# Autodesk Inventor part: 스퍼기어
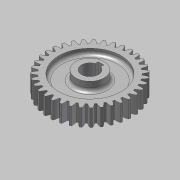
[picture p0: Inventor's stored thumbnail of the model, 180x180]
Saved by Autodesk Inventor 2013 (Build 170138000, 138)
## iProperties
Created: 2013-08
Part Number: 스퍼기어
Material: 강
Document SubType Name: Modeling
Designer: 한국산업디자인학원
Categories: <?xml version="1.0" encoding="UTF-16"?> <MemberInstance><Categories><FamilyTemplate><FamilyTemplateParameter ValueType="xs:double" Id="1" ObjectReferenceKey="da
Density: 1 g/cm^3
CustomPartVersion: 1
Author: 한국산업디자인학원
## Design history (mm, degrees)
sketch "Sketch1"
  geometry: C1 r 37 at (0, 0)
  constraints: 1 centre point
  dimensions: "d0" = 74 diameter of C1 (= da_da)
extrude "Extrusion1" new body sketch "Sketch1" distance "d1" = 15 (= da_b); taper "d2" = 0 deg
workplane "Work Plane2"
feature "피치 지름" dims "d4" = 10, "d5" = 0
workplane "Work Plane8"
workplane "Work Plane9"
feature "스퍼 기어" dims "da_b" = 15, "da_d" = 70, "da_aw" = 70, "da_da" = 74, "da_df" = 65, "da_dw" = 70, angle "da_beta" = 0 deg, "da_lefttooth" = 0, "da_righttooth" = 0
node "작업 평면11"
sketch "스케치3"
  geometry: C1 r 12.5 at (0, 0); 1 further point
  constraints: 1 centre point, 1 coincident
  dimensions: "d50" = 25 diameter of C1
extrude "돌출2" join sketch "스케치3" distance "d51" = 31; taper "d52" = 0 deg
hole "구멍1" diameter "d55" = 15; stored, may be unused: countersink angle "d59" = 90 deg, drill point angle "d61" = 0 deg; dims "d53" = 10, "d54" = 10, "d56" = 6, "d57" = 4, "d58" = 2, "d60" = 8
sketch "스케치4"
  geometry: L1 (0, 28.305)-(0, -28.305); L2 (35, 15)-(35, 0) reference; L3 (35, 0)-(12.5, 0) reference; L4 (12.5, 0)-(12.5, -13) reference; L5 (12.5, -13)-(7.5, -13) reference; L6 (7.5, -13)-(7.5, 18) reference; L7 (7.5, 18)-(12.5, 18) reference; L8 (12.5, 18)-(12.5, 15) reference; L9 (12.5, 15)-(35, 15) reference; L10 (-35, 0)-(-35, 15) reference; L11 (-35, 15)-(-12.5, 15) reference; L12 (-12.5, 15)-(-12.5, 18) reference; L13 (-12.5, 18)-(-7.5, 18) reference; L14 (-7.5, 18)-(-7.5, -13) reference; L15 (-7.5, -13)-(-12.5, -13) reference; L16 (-12.5, -13)-(-12.5, 0) reference; L17 (-12.5, 0)-(-35, 0) reference; L18 (27.5, 15)-(12.5, 15); L19 (12.5, 15)-(12.5, 10); L20 (12.5, 10)-(27.5, 10); L21 (27.5, 10)-(27.5, 15); L22 (27.5, 0)-(12.5, 0); L23 (12.5, 0)-(12.5, 5); L24 (12.5, 5)-(27.5, 5); L25 (27.5, 5)-(27.5, 0); 2 further points
  constraints: 18 end point, 4 parallel, 2 collinear, 2 horizontal, 2 perpendicular, 2 point on line, 1 coincident, 1 midpoint, 1 vertical
  dimensions: "d62" = 5 distance of L20.end L18.start; "d64" = 5 distance of L24.end L22.start; "d65" = 55 diameter of L21 L1; "d66" = 25 diameter of L19 L1
revolve "회전1" sketch "스케치4" stored, may be unused: angle "d67" = 90 deg
sketch "스케치5"
  geometry: L1 (-2.5, 9.8)-(2.5, 9.8); L2 (2.5, 9.8)-(2.5, 4.8); L3 (2.5, 4.8)-(-2.5, 4.8); L4 (-2.5, 4.8)-(-2.5, 9.8); C1 r 7.5 at (0, 0) reference
  constraints: 8 end point, 2 parallel, 1 horizontal, 1 perpendicular
  dimensions: "d68" = 5 distance of L2.end L3.end; "d69" = 5 distance of L1.end L2.end; "d70" = 2.5 distance from line of C1.centre L4; "d71" = 9.8 distance from line of C1.centre L1
extrude "돌출3" cut sketch "스케치5" stored distance "d72" = 31; taper "d73" = 0 deg
fillet "모깎기1" dims "d74" = 3
body "Solid1"
sketch "Sketch2"
  geometry: C1 r 37 at (0, 0) reference; C2 r 35 at (0, 0)
  constraints: 1 centre point, 1 coincident
  dimensions: "d3" = 70 diameter of C2 (= da_dw)
body "Srf1"
node "절단 모서리 투영1"
other parameters: "d17" = 0, "d34" = 0.8976 (computed from da_z), "d39" = 0, "d41" = 0, "d47" = 0, "d48" = 0, "d49" = 3
